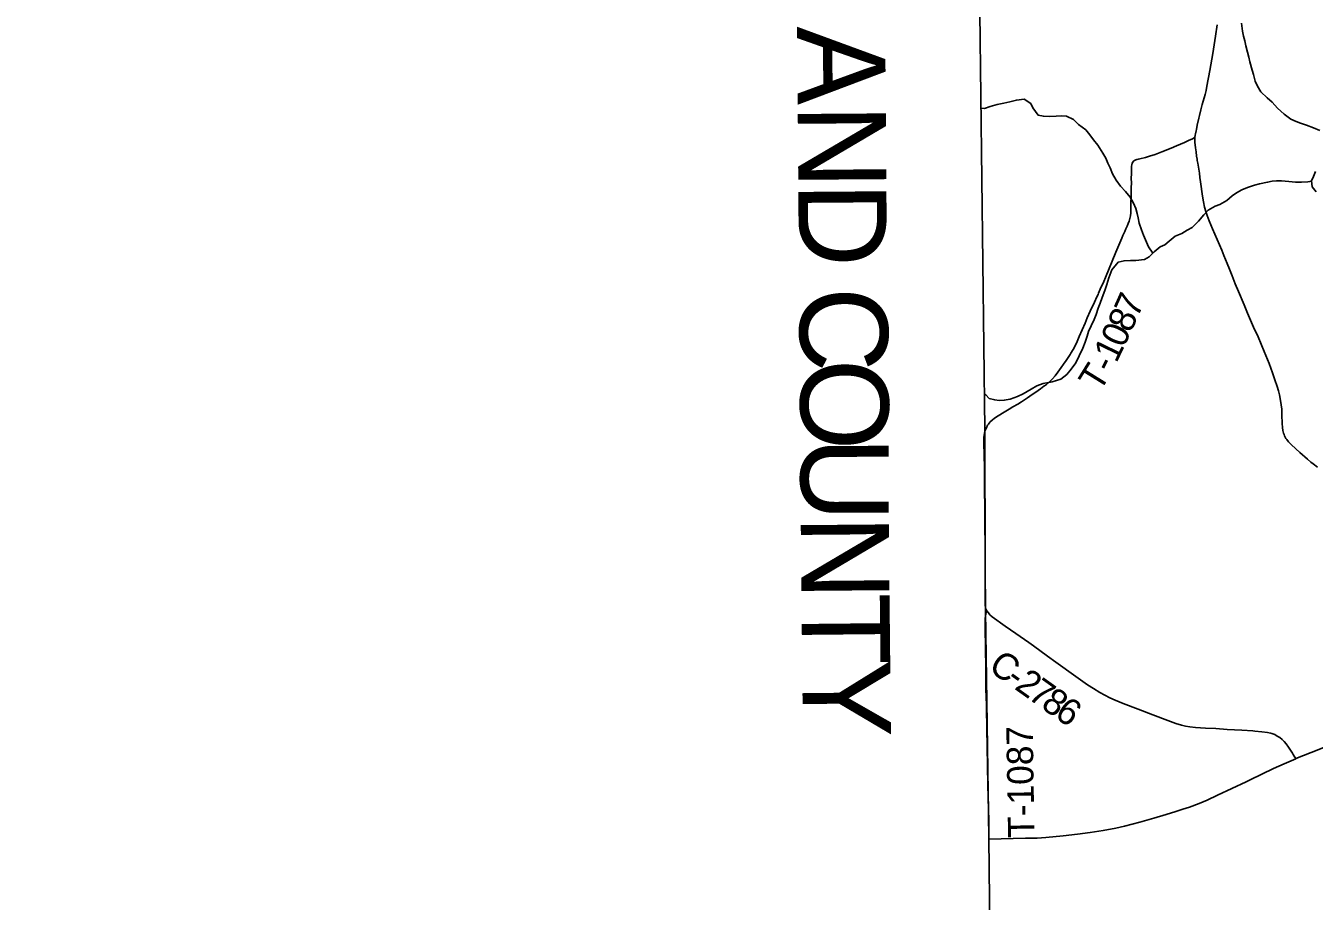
# Model space of a CAD drawing. Extents: x 1874609 to 2204689, y 815661 to 1281160.
# Drawn here: x 2002342 to 2016966, y 965278 to 975217 of the extents above; entities that cross this region are included whole.
import ezdxf

# ---------------------------------------------------------------- set-up
doc = ezdxf.new("R2010")
doc.units = 0
for name, color, linetype in [('GM_X_Adjacent_County', 7, 'Continuous'), ('GM_X_Adjacent_County_Text', 7, 'Continuous'), ('GM_X_County', 7, 'Continuous'), ('GM_X_County_Road', 7, 'Continuous'), ('GM_X_County_Road_Text', 7, 'Continuous'), ('GM_X_Major_River', 7, 'Continuous'), ('GM_X_Minor_River', 7, 'Continuous'), ('GM_X_State_Route', 7, 'Continuous'), ('GM_X_Township', 7, 'Continuous'), ('GM_X_Township_Road', 7, 'Continuous'), ('GM_X_Township_Road_Text', 7, 'Continuous')]:
    doc.layers.add(name, color=color, linetype=linetype)

msp = doc.modelspace()

# ---------------------------------------------------------------- linework, layer by layer
at = {"layer": 'GM_X_Adjacent_County'}
msp.add_lwpolyline([(2002342, 999536), (2002395, 993238), (2002881, 993241), (2003206, 993234), (2004504, 993233), (2007698, 993231), (2008414, 993238), (2008503, 993236), (2013055, 993227), (2013045, 990449), (2013083, 985682), (2013088, 985095), (2013122, 980772), (2013145, 977956), (2013158, 976319), (2013226, 970636), (2013231, 969069), (2013234, 968580), (2013273, 965999), (2013327, 961098), (2013338, 960130), (2013382, 956206), (2013389, 955699), (2013479, 950530)], dxfattribs=at)
at = {"layer": 'GM_X_County'}
msp.add_lwpolyline([(2013479, 950530), (2013389, 955699), (2013382, 956206), (2013338, 960130), (2013327, 961098), (2013273, 965999), (2013234, 968580), (2013231, 969069), (2013226, 970636), (2013158, 976319), (2013145, 977956), (2013122, 980772), (2013088, 985095), (2013083, 985682), (2013045, 990449), (2013055, 993227), (2008503, 993236), (2008414, 993238), (2007698, 993231), (2004504, 993233), (2003206, 993234), (2002881, 993241), (2002395, 993238), (2002342, 999536)], dxfattribs=at)
at = {"layer": 'GM_X_County_Road'}
for points in [[(2015612, 973948), (2015616, 973976), (2015619, 973991), (2015625, 974023), (2015628, 974039), (2015637, 974087), (2015655, 974167), (2015663, 974199), (2015678, 974262), (2015695, 974325), (2015728, 974436), (2015739, 974484), (2015748, 974532), (2015781, 974710), (2015814, 974904), (2015831, 975001), (2015846, 975098), (2015864, 975228)], [(2017004, 970207), (2016952, 970244), (2016927, 970264), (2016890, 970296), (2016804, 970371), (2016708, 970460), (2016673, 970495), (2016653, 970520), (2016644, 970533), (2016636, 970547), (2016629, 970562), (2016623, 970576), (2016617, 970592), (2016609, 970623), (2016605, 970655), (2016602, 970703), (2016599, 970800), (2016596, 970865), (2016591, 970914), (2016583, 970962), (2016571, 971027), (2016560, 971074), (2016546, 971121), (2016520, 971199), (2016492, 971276), (2016453, 971382), (2016397, 971519), (2016329, 971685), (2016278, 971794), (2016210, 971956), (2016169, 972049), (2016105, 972200), (2016070, 972289), (2016035, 972377), (2016003, 972455), (2015976, 972517), (2015941, 972609), (2015916, 972670), (2015890, 972730), (2015864, 972790), (2015812, 972911), (2015773, 973001), (2015750, 973062), (2015735, 973108), (2015722, 973156), (2015708, 973220), (2015697, 973284), (2015676, 973447), (2015669, 973496), (2015662, 973544), (2015643, 973656), (2015638, 973688), (2015636, 973704), (2015631, 973737), (2015624, 973785), (2015618, 973833), (2015611, 973897), (2015611, 973928), (2015611, 973944), (2015612, 973948)], [(2013230, 969049), (2013230, 969010), (2013230, 968944), (2013230, 968686), (2013232, 968640), (2013235, 968612), (2013240, 968596), (2013251, 968575)], [(2013251, 968575), (2013267, 968553), (2013283, 968530), (2013309, 968506), (2013456, 968402), (2013578, 968318), (2013726, 968214), (2013779, 968176), (2013939, 968061), (2014032, 967993), (2014259, 967830), (2014393, 967736), (2014461, 967691), (2014531, 967648), (2014588, 967616), (2014646, 967587), (2014706, 967560), (2014797, 967523), (2014966, 967459), (2015135, 967394), (2015303, 967329), (2015396, 967296), (2015458, 967277), (2015506, 967265), (2015554, 967257), (2015619, 967250), (2015733, 967243), (2015847, 967237), (2015978, 967228), (2016142, 967218), (2016269, 967211)], [(2016269, 967211), (2016290, 967209), (2016372, 967202), (2016437, 967193), (2016470, 967186), (2016486, 967181), (2016517, 967169), (2016546, 967153), (2016574, 967135), (2016600, 967114), (2016624, 967091), (2016646, 967066), (2016675, 967026), (2016720, 966957), (2016728, 966943), (2016757, 966896)]]:
    msp.add_lwpolyline(points, dxfattribs=at)
at = {"layer": 'GM_X_Major_River'}
msp.add_lwpolyline([(2016980, 973561), (2016956, 973507), (2016936, 973457), (2016944, 973389), (2016988, 973333)], dxfattribs=at)
at = {"layer": 'GM_X_Minor_River'}
for points in [[(2017031, 974029), (2016959, 974059), (2016879, 974089), (2016811, 974113), (2016759, 974129), (2016700, 974157), (2016624, 974215), (2016548, 974281), (2016490, 974348), (2016432, 974398), (2016358, 974468), (2016320, 974532), (2016294, 974588), (2016276, 974662), (2016260, 974713), (2016236, 974809), (2016224, 974861), (2016210, 974919), (2016190, 974991), (2016178, 975047), (2016164, 975098), (2016150, 975154), (2016139, 975248)], [(2015134, 972636), (2015085, 972708), (2015063, 972760), (2015029, 972839), (2015005, 972901), (2014979, 972977), (2014966, 973037), (2014956, 973087), (2014940, 973141), (2014916, 973204), (2014878, 973272), (2014822, 973334), (2014768, 973396), (2014717, 973464), (2014677, 973535), (2014650, 973603), (2014624, 973659), (2014600, 973713), (2014566, 973771), (2014510, 973861), (2014459, 973922), (2014419, 973978), (2014375, 974034), (2014289, 974098), (2014233, 974152), (2014153, 974192), (2014099, 974194), (2014037, 974190), (2013963, 974188), (2013891, 974190), (2013832, 974203), (2013772, 974285), (2013748, 974335), (2013674, 974385), (2013586, 974373), (2013510, 974353), (2013442, 974339), (2013366, 974325), (2013289, 974301), (2013225, 974279), (2013185, 974281)], [(2016937, 973454), (2016892, 973447), (2016820, 973443), (2016754, 973443), (2016678, 973449), (2016593, 973457), (2016539, 973457), (2016489, 973453), (2016437, 973441), (2016345, 973423), (2016289, 973407), (2016207, 973381), (2016142, 973353), (2016084, 973319), (2016034, 973285), (2015972, 973235), (2015894, 973187), (2015842, 973169), (2015763, 973125), (2015711, 973071), (2015651, 972997), (2015579, 972927), (2015525, 972895), (2015462, 972860), (2015386, 972828), (2015320, 972772), (2015270, 972730), (2015216, 972706), (2015149, 972652), (2015093, 972594), (2015039, 972562), (2014941, 972552), (2014879, 972552), (2014807, 972550), (2014740, 972532), (2014670, 972446), (2014634, 972356), (2014612, 972281), (2014588, 972213), (2014560, 972133), (2014536, 972069), (2014515, 972011), (2014491, 971939), (2014469, 971883), (2014435, 971810), (2014405, 971746), (2014387, 971694), (2014365, 971626), (2014341, 971556), (2014298, 971468), (2014260, 971391), (2014206, 971317), (2014156, 971257), (2014088, 971203), (2013993, 971175), (2013889, 971155), (2013817, 971131), (2013751, 971091), (2013661, 971039), (2013598, 971007), (2013514, 970977), (2013448, 970965), (2013390, 970963), (2013340, 970969), (2013278, 970985), (2013237, 971026), (2013221, 971037)]]:
    msp.add_lwpolyline(points, dxfattribs=at)
at = {"layer": 'GM_X_State_Route'}
for points in [[(2016239, 966657), (2016504, 966784), (2016623, 966839), (2016757, 966896), (2016758, 966897), (2017016, 967001), (2017305, 967118), (2017441, 967175), (2017530, 967216), (2017618, 967260), (2017690, 967300), (2017760, 967344), (2017827, 967390), (2017893, 967439), (2017944, 967480), (2018006, 967534), (2018065, 967591), (2018110, 967638), (2018165, 967700), (2018228, 967775), (2018267, 967828), (2018323, 967908), (2018414, 968047)], [(2013273, 965984), (2013690, 965992), (2013821, 965995), (2013920, 966001), (2014115, 966019), (2014278, 966038), (2014424, 966059), (2014570, 966082), (2014715, 966109), (2014812, 966129), (2014986, 966174), (2015144, 966219), (2015285, 966261), (2015394, 966297), (2015473, 966321), (2015550, 966347), (2015658, 966388), (2015749, 966426), (2015868, 966480), (2016194, 966635), (2016239, 966657)]]:
    msp.add_lwpolyline(points, dxfattribs=at)
at = {"layer": 'GM_X_Township'}
msp.add_lwpolyline([(2017186, 961107), (2013327, 961098), (2013273, 965999), (2013234, 968580), (2013231, 969069), (2013226, 970636), (2013158, 976319)], dxfattribs=at)
at = {"layer": 'GM_X_Township_Road'}
for points in [[(2013226, 970603), (2013232, 970624), (2013237, 970637), (2013244, 970652), (2013259, 970681), (2013268, 970694), (2013278, 970707), (2013288, 970719), (2013312, 970741), (2013338, 970761), (2013378, 970788), (2013447, 970831), (2013503, 970864), (2013545, 970889), (2013601, 970922), (2013643, 970948), (2013711, 970993), (2013739, 971012), (2013765, 971031), (2013805, 971059), (2013858, 971096), (2013896, 971125), (2013922, 971141), (2013960, 971173), (2013994, 971207), (2014026, 971244), (2014055, 971283), (2014093, 971337), (2014120, 971377), (2014150, 971416), (2014195, 971485), (2014204, 971499), (2014229, 971542), (2014266, 971615), (2014299, 971690), (2014364, 971841), (2014390, 971900), (2014424, 971975), (2014472, 972079), (2014500, 972138), (2014513, 972167), (2014518, 972181), (2014537, 972225), (2014576, 972314), (2014595, 972359), (2014715, 972645), (2014783, 972807), (2014795, 972836), (2014816, 972881), (2014829, 972911), (2014842, 972941), (2014854, 972971), (2014864, 973000), (2014871, 973029), (2014879, 973061), (2014883, 973093), (2014884, 973127), (2014884, 973181), (2014887, 973305), (2014889, 973374), (2014890, 973436), (2014889, 973481), (2014890, 973542), (2014890, 973591), (2014892, 973624), (2014895, 973640), (2014899, 973656), (2014906, 973670), (2014913, 973681), (2014924, 973689), (2014939, 973696), (2014954, 973700), (2014970, 973704), (2014986, 973707), (2015050, 973723), (2015097, 973736), (2015159, 973756), (2015237, 973784), (2015343, 973826), (2015403, 973853), (2015493, 973893), (2015546, 973917), (2015575, 973930), (2015612, 973948)], [(2013230, 969049), (2013230, 969145), (2013230, 969203), (2013230, 969218), (2013230, 969234), (2013230, 969300), (2013230, 969365), (2013229, 969398), (2013229, 969414), (2013228, 969448), (2013226, 969709), (2013225, 969988), (2013222, 970200), (2013219, 970347), (2013216, 970477), (2013216, 970540), (2013219, 970571), (2013222, 970587), (2013225, 970600), (2013226, 970603)], [(2013273, 965984), (2013271, 966159), (2013267, 966356), (2013262, 966585), (2013258, 966831), (2013255, 967011), (2013249, 967256), (2013245, 967451), (2013244, 967516), (2013242, 967582), (2013240, 967698), (2013238, 967856), (2013238, 967987), (2013235, 968085), (2013233, 968223), (2013232, 968311), (2013232, 968478), (2013232, 968495), (2013234, 968512), (2013235, 968524), (2013237, 968535), (2013240, 968546), (2013243, 968557), (2013251, 968575)]]:
    msp.add_lwpolyline(points, dxfattribs=at)

# ---------------------------------------------------------------- texts
at = {"layer": 'GM_X_Adjacent_County_Text'}
for s, rotation, p in [('A', 270.4155, (2011096, 975209)), ('N', 270.4194, (2011103, 974325)), ('D', 270.4593, (2011109, 973440)), ('C', 270.8048, (2011119, 972245)), ('O', 270.3404, (2011131, 971433)), ('U', 270.0816, (2011136, 970550)), ('N', 270.5088, (2011137, 969657)), ('T', 270.6066, (2011145, 968771)), ('Y', 270.6268, (2011153, 968023))]:
    msp.add_text(s, height=1000, rotation=rotation, dxfattribs=at).set_placement(p)
at = {"layer": 'GM_X_County_Road_Text'}
for s, rotation, p in [('C', 324.592, (2013253, 967907)), ('-', 324.5829, (2013452, 967765)), ('2', 324.5449, (2013552, 967695)), ('7', 324.4656, (2013701, 967588)), ('8', 324.4916, (2013850, 967482)), ('6', 325.5344, (2014005, 967372))]:
    msp.add_text(s, height=300, rotation=rotation, dxfattribs=at).set_placement(p)
at = {"layer": 'GM_X_Township_Road_Text'}
for s, rotation, p in [('7', 65.8609, (2014957, 971890)), ('8', 65.7651, (2014881, 971721)), ('0', 65.3763, (2014803, 971551)), ('1', 64.1481, (2014719, 971379)), ('T', 58.2358, (2014530, 971048)), ('-', 63.3756, (2014662, 971265)), ('T-1087', 90.9364, (2013791, 965999))]:
    msp.add_text(s, height=300, rotation=rotation, dxfattribs=at).set_placement(p)

doc.saveas('drawing.dxf')
